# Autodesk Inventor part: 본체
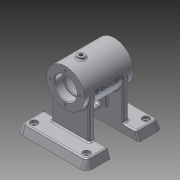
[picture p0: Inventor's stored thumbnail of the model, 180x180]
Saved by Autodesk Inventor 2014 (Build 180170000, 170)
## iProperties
Created: 2016-07
Part Number: 본체
Material: 알루미늄 6061
Document SubType Name: Modeling
Designer: USER
Density: 2.71 g/cm^3
Appearance: 알루미늄 - 평지
Mass: 500.05 g
Surface Area: 540.599 cm^2
Volume: 184.52 cm^3
Author: USER
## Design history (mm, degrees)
sketch "스케치1"
  geometry: L1 (0, 0)-(100, 0); L2 (100, 0)-(100, 110); L3 (100, 110)-(0, 110); L4 (0, 110)-(0, 0)
  constraints: 8 end point, 1 horizontal, 1 parallel, 1 perpendicular
  dimensions: "d0" = 100 distance of L1.start L1.end; "d1" = 110 distance of L1.end L2.end; "d2" = 100 distance of L2.end L3.end
extrude "돌출1" new body sketch "스케치1" distance "d3" = 12; taper "d4" = -20 deg
sketch "스케치2"
  geometry: L1 (4.368, 4.368)-(4.368, 105.632) reference; L2 (95.632, 105.632)-(95.632, 4.368) reference; L3 (4.368, 105.632)-(95.632, 105.632) reference; L4 (-24.368, 35)-(125.632, 35); L5 (125.632, 35)-(125.632, 75); L6 (125.632, 75)-(-24.368, 75); L7 (-24.368, 75)-(-24.368, 35); 3 further points
  constraints: 8 end point, 3 perpendicular, 2 midpoint, 1 horizontal alignment, 1 parallel
  dimensions: "d5" = 40 distance of L4.end L5.end; "d6" = 150 distance of L5.end L6.end; "d7" = 30 distance between parallel lines of L2 L5
extrude "돌출2" cut sketch "스케치2" distance "d8" = 12; taper "d9" = 0 deg
sketch "스케치3"
  geometry: L1 (95.632, 35)-(4.368, 35) reference; L2 (95.632, 4.368)-(4.368, 4.368) reference; L3 (4.368, 75)-(95.632, 75) reference; L4 (95.632, 105.632)-(95.632, 75) reference; L5 (4.368, 105.632)-(95.632, 105.632) reference; L6 (4.368, 75)-(4.368, 105.632) reference; L7 (23, 35)-(23, 27); L8 (23, 27)-(77, 27); L9 (77, 27)-(77, 35); L10 (23, 35)-(77, 35); L11 (23, 75)-(23, 83); L12 (23, 83)-(77, 83); L13 (77, 83)-(77, 75); L14 (23, 75)-(77, 75); 5 further points
  constraints: 16 end point, 4 midpoint, 4 perpendicular, 4 point on line, 2 collinear, 2 parallel, 2 vertical alignment
  dimensions: "d10" = 8 distance of L7.start L7.end; "d11" = 54 distance of L7.end L8.end; "d12" = 8 distance of L11.start L11.end; "d13" = 54 distance of L11.end L12.end
extrude "돌출3" join sketch "스케치3" distance "d14" = 58; taper "d15" = 0 deg
node "작업 평면1"
sketch "스케치4"
  geometry: L1 (-23, -12)-(-18.632, 0) reference; L2 (77, -12)-(-23, -12) reference; L3 (72.632, 0)-(77, -12) reference; L4 (54, 0)-(72.632, 0) reference; L5 (54, 0)-(54, 58) reference; L6 (0, 58)-(54, 58) reference; L7 (0, 0)-(0, 58) reference; L8 (-18.632, 0)-(0, 0) reference; C1 r 27 at (27, 58); 2 further points
  constraints: 2 coincident, 1 centre point, 1 midpoint
  dimensions: "d16" = 54 diameter of C1
extrude "돌출4" join sketch "스케치4" stored distance "d17" = 70; taper "d18" = 0 deg
node "작업 평면2"
sketch "스케치5"
  geometry: L1 (-85, -7)-(-31, -7) reference; L2 (-31, 63)-(-85, 63) reference; L3 (-58, 0)-(-58, 8) reference; L4 (-58, 8)-(-58, 8) reference; L5 (-58, 8)-(-58, 0) reference; L6 (-58, 0)-(-58, 0) reference; L7 (-58, 56)-(-58, 48) reference; L8 (-58, 48)-(-58, 48) reference; L9 (-58, 48)-(-58, 56) reference; L10 (-58, 56)-(-58, 56) reference; L11 (0, 0)-(0, 8) reference; L12 (0, 0)-(-58, 0) reference; L13 (-58, 8)-(-58, 0) reference; L14 (0, 8)-(-58, 8) reference; L15 (0, 48)-(0, 56) reference; L16 (0, 48)-(-58, 48) reference; L17 (-58, 56)-(-58, 48) reference; L18 (0, 56)-(-58, 56) reference; L19 (-85, 63)-(-85, -7) reference; L20 (-31, 63)-(-31, -7) reference; L21 (-10, 8)-(-10, 48); L22 (-58, 8)-(-10, 8); L23 (-58, 48)-(-10, 48); L24 (-58, 8)-(-58, 48); 1 further point
  constraints: 8 end point, 2 collinear, 2 perpendicular, 2 point on line
  dimensions: "d20" = 48 distance of L13.start L21.start
extrude "돌출5" join sketch "스케치5" stored distance "d21" = 8; taper "d22" = 0 deg
sketch "스케치6"
  geometry: L1 (31.298, 48)-(31.298, 8) reference; L2 (10, 48)-(10, 8) reference; L3 (20, 36)-(20, 20); L4 (16.5, 36)-(16.5, 20); L5 (23.5, 20)-(23.5, 36); L6 (-12, 8)-(-12, -27) reference; A1 r 3.5 centre (20, 36) between (23.5, 36) and (16.5, 36); A2 r 3.5 centre (20, 20) between (16.5, 20) and (23.5, 20); 2 further points
  constraints: 8 end point, 4 point on circle, 4 tangent, 2 centre point, 2 midpoint, 2 parallel, 1 horizontal alignment
  dimensions: "d23" = 3.5 radius of A2; "d24" = 23 dimension on A2 A1; "d25" = 32 distance from line of point (20, 28) L6
extrude "돌출6" cut sketch "스케치6" distance "d26" = 8; taper "d27" = 0 deg
sketch "스케치7"
  geometry: C1 r 27 at (0, 0) reference; C2 r 16 at (0, 0); 1 further point
  constraints: 1 centre point, 1 coincident
  dimensions: "d28" = 32 diameter of C2
extrude "돌출7" cut sketch "스케치7" distance "d29" = 12; taper "d30" = 0 deg
sketch "스케치8"
  geometry: C1 r 27 at (0, 0) reference; C2 r 16 at (0, 0); 1 further point
  constraints: 1 centre point, 1 coincident
  dimensions: "d31" = 32 diameter of C2
extrude "돌출8" cut sketch "스케치8" distance "d32" = 12; taper "d33" = 0 deg
node "작업 평면3"
sketch "스케치9"
  geometry: C1 r 16 at (0, 0) reference; C2 r 22 at (0, 0); 1 further point
  constraints: 1 centre point, 1 coincident
  dimensions: "d34" = 44 diameter of C2
extrude "돌출9" cut sketch "스케치9" stored distance "d35" = 42; taper "d36" = 0 deg
sketch "스케치10"
  geometry: C1 r 16 at (0, 0) reference; C2 r 14 at (0, 0); 1 further point
  constraints: 1 centre point, 1 coincident
  dimensions: "d37" = 28 diameter of C2
extrude "돌출10" cut sketch "스케치10" stored distance "d38" = 42; taper "d39" = 0 deg
node "작업 평면5"
  node "작업 평면4"
sketch "스케치11"
  geometry: L1 (4, -20)-(4, 20) reference; L2 (27, 20)-(4, 20) reference; L3 (27, 20)-(27, 28) reference; L4 (-27, 28)-(27, 28) reference; L5 (-27, 28)-(-27, 20) reference; L6 (-4, 20)-(-27, 20) reference; L7 (-4, 20)-(-4, -20) reference; L8 (-27, -20)-(-4, -20) reference; L9 (-27, -20)-(-27, -28) reference; L10 (27, -28)-(-27, -28) reference; L11 (27, -28)-(27, -20) reference; L12 (4, -20)-(27, -20) reference; L13 (-27, -35)-(27, -35) reference; L14 (27, 35)-(-27, 35) reference; C1 r 5 at (0, -13); 2 further points
  constraints: 1 centre point, 1 midpoint, 1 vertical alignment
  dimensions: "d41" = 10 diameter of C1; "d42" = 22 distance of point (0, -35) C1.centre
extrude "돌출11" join sketch "스케치11" stored distance "d43" = 42; taper "d44" = 0 deg
sketch "스케치12"
  geometry: C1 r 5 at (0, 0) reference; 2 further points
  constraints: 1 coincident
hole "구멍1" sketch "스케치12" at (0, 0) diameter "d45" = 5.188; stored, may be unused: countersink angle "d49" = 90 deg, drill point angle "d51" = 118 deg; dims "d46" = 10, "d47" = 4, "d48" = 2, "d50" = 10
sketch "스케치13"
  geometry: L1 (100, 75)-(0, 75) reference; L2 (0, 110)-(0, 75) reference; L3 (100, 110)-(0, 110) reference; L4 (100, 75)-(100, 110) reference; L5 (0, 35)-(0, 0) reference; L6 (0, 0)-(100, 0) reference; 4 further points
  constraints: 2 horizontal alignment, 2 vertical alignment
  dimensions: "d52" = 75 distance of point (87.5, 12.5) point (12.5, 12.5); "d53" = 85 distance of point (87.5, 12.5) point (87.5, 97.5); "d56" = 12.5 distance from line of point (12.5, 12.5) L5; "d57" = 12.5 distance from line of L6 point (12.5, 12.5)
hole "구멍2" sketch "스케치13" at (12.5, 97.5), (87.5, 97.5), (87.5, 12.5), (12.5, 12.5) diameter "d58" = 6; stored, may be unused: countersink angle "d62" = 90 deg, drill point angle "d64" = 118 deg; dims "d59" = 10, "d60" = 10, "d61" = 4, "d63" = 10
node "작업 평면6"
sketch "스케치14"
  geometry: L1 (0, 0)-(0, -27); L2 (0, 0)-(14.308, -22.897); C1 r 16 at (0, 0) reference; A1 r 27 centre (0, 0) between (4, -26.702) and (27, 0) reference; A2 r 27 centre (0, 0) between (-27, 0) and (27, 0) reference; A3 r 27 centre (0, 0) between (0, -27) and (14.308, -22.897) reference; 2 further points
  constraints: 4 end point, 4 point on circle, 1 coincident
  dimensions: "d66" = 32 deg angle of L1 L2
  node "투영된 루프9"
node "작업 평면7"
sketch "스케치17" dims "d77" = 42
  geometry: C1 r 16 at (0, 0) reference; C2 r 27 at (0, 0) reference; 3 further points
  constraints: 2 vertical alignment, 1 coincident, 2 other
hole "구멍4" sketch "스케치17" at (0, 21) diameter "d78" = 3.459; stored, may be unused: countersink angle "d82" = 90 deg, drill point angle "d84" = 118 deg; dims "d79" = 8, "d80" = 10, "d81" = 4, "d83" = 10
node "작업 평면8"
node "작업 평면9"
sketch "스케치18"
  geometry: L1 (35, 27)-(-35, 27) reference; L2 (35, -27)-(35, 27) reference; L3 (-35, 27)-(-35, -27) reference; L4 (35, -27)-(-35, -27) reference; 2 further points
  constraints: 1 other
  dimensions: "d88" = 27 distance from line of L1 point (0, 0); "d89" = 35 distance from line of L3 point (0, 0)
feature "엠보싱1" sketch "스케치18" dims "d90" = 0.5, "d91" = 0
node "작업 평면10"
sketch "스케치19"
  geometry: L1 (0, 0)-(0, -27); L2 (0, 0)-(-14.308, -22.897); C1 r 1.73 at (21, 0) reference; C2 r 1.73 at (0, -21) reference; C3 r 1.73 at (-21, 0) reference; C4 r 1.73 at (0, 21) reference; C5 r 16 at (0, 0) reference; A1 r 27 centre (0, 0) between (-14.308, -22.897) and (0, -27) reference; 2 further points
  constraints: 4 end point, 2 point on circle, 1 coincident, 1 vertical
  dimensions: "d92" = 32 deg angle of L1 L2
  node "투영된 루프12"
node "작업 평면11"
sketch "스케치20"
  geometry: L1 (-14.566, -21.692)-(-17.463, -21.692) reference; L2 (-17.463, -21.692)-(-17.463, -21.912) reference; L3 (-17.463, -21.912)-(-15.014, -21.912) reference; L4 (-15.014, -21.912)-(-15.014, -22.577) reference; L5 (-15.014, -22.577)-(-17.198, -22.577) reference; L6 (-17.198, -22.577)-(-17.198, -22.78) reference; L7 (-17.198, -22.78)-(-15.014, -22.78) reference; L8 (-15.014, -22.78)-(-15.014, -23.456) reference; L9 (-14.566, -23.651)-(-14.566, -21.692) reference; L10 (-9.803, -22.152)-(-10.834, -22.152) reference; L11 (-10.834, -22.152)-(-10.834, -21.265) reference; L12 (-10.834, -21.265)-(-11.208, -21.265) reference; L13 (-11.289, -21.41)-(-11.289, -23.615) reference; L14 (-11.289, -23.615)-(-10.834, -23.615) reference; L15 (-10.834, -23.615)-(-10.834, -22.348) reference; L16 (-10.834, -22.348)-(-9.803, -22.348) reference; L17 (-9.803, -22.348)-(-9.803, -22.152) reference; L18 (-8.67, -21.381)-(-9.071, -21.381) reference; L19 (0.488, -24.174)-(0.488, -21.793) reference; L20 (0.488, -21.793)-(2.042, -21.793) reference; L21 (2.042, -21.793)-(2.042, -21.546) reference; L22 (2.042, -21.546)-(-1.526, -21.546) reference; L23 (-1.526, -21.546)-(-1.526, -21.793) reference; L24 (-1.526, -21.793)-(0.034, -21.793) reference; L25 (0.034, -21.793)-(0.034, -24.174) reference; L26 (0.034, -24.174)-(0.488, -24.174) reference; L27 (4.878, -21.546)-(4.335, -21.546) reference; L28 (2.436, -24.174)-(2.917, -24.174) reference; L29 (3.474, -23.456)-(5.726, -23.456) reference; L30 (6.296, -24.174)-(6.777, -24.174) reference; L31 (18.853, -21.307)-(17.374, -21.307) reference; L32 (17.374, -21.307)-(17.374, -21.521) reference; L33 (17.374, -21.521)-(18.853, -21.521) reference; L34 (18.853, -21.521)-(18.853, -21.307) reference; L35 (15.061, -21.332)-(15.061, -22.547) reference; L36 (15.061, -22.547)-(13.942, -22.547) reference; L37 (13.942, -22.547)-(13.942, -22.761) reference; L38 (13.942, -22.761)-(15.061, -22.761) reference; L39 (15.061, -22.761)-(15.061, -23.651) reference; L40 (15.061, -23.651)-(15.536, -23.651) reference; L41 (15.536, -23.651)-(15.536, -21.168) reference; L42 (15.536, -21.168)-(15.231, -21.168) reference; L43 (18.731, -23.612)-(18.731, -24.095) reference; L44 (18.731, -24.095)-(14.844, -24.095) reference; L45 (14.844, -24.095)-(14.844, -24.264) reference; L46 (14.844, -24.264)-(19.193, -24.264) reference; L47 (19.193, -24.264)-(19.193, -23.506) reference; L48 (19.193, -23.506)-(18.84, -23.506) reference; L49 (20.047, -21.793)-(16.282, -21.793) reference; L50 (16.282, -21.793)-(16.282, -21.999) reference; L51 (16.282, -21.999)-(20.047, -21.999) reference; L52 (20.047, -21.999)-(20.047, -21.793) reference; L53 (13.311, -22.495)-(8.942, -22.495) reference; L54 (8.657, -21.53)-(12.463, -21.53) reference; L55 (12.463, -21.53)-(12.463, -21.298) reference; L56 (12.463, -21.298)-(8.175, -21.298) reference; L57 (8.446, -22.495)-(7.307, -22.495) reference; L58 (7.307, -22.495)-(7.307, -22.699) reference; L59 (7.307, -22.699)-(10.095, -22.699) reference; L60 (10.095, -22.699)-(10.095, -23.337) reference; L61 (10.095, -23.337)-(8.284, -23.337) reference; L62 (8.284, -23.337)-(8.284, -24.332) reference; L63 (8.284, -24.332)-(8.745, -24.332) reference; L64 (8.745, -24.332)-(8.745, -23.522) reference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; C1 r 6 at (0, 0); 63 further points
  constraints: 2 midpoint, 1 centre point, 1 horizontal alignment, 1 vertical alignment, 76 other
  dimensions: "d93" = 12 diameter of C1
extrude "돌출13" join sketch "스케치20" stored distance "d94" = 6; taper "d95" = 0 deg
sketch "스케치21"
  geometry: C1 r 6 at (0, 0) reference; 2 further points
  constraints: 1 coincident
hole "구멍5" sketch "스케치21" at (0, 0) diameter "d96" = 5.188; stored, may be unused: countersink angle "d100" = 90 deg, drill point angle "d102" = 118 deg; dims "d97" = 10, "d98" = 10, "d99" = 4, "d101" = 10
fillet "모깎기1" dims "d103" = 10, "d104" = 5, "d105" = 10, "d106" = 5, "d107" = 10, "d108" = 5, "d109" = 10, "d110" = 5
fillet "모깎기2" dims "d111" = 2
chamfer "모따기1" distance "d112" = 1; stored, may be unused: second distance "d113" = 2, angle "d114" = 45 deg
fillet "모깎기3" dims "d115" = 3
fillet "모깎기4" dims "d116" = 0.3
node "솔리드1"
pattern_circular "원형 패턴1" dims angle "d86" = 360 deg
mirror "대칭1"
node "투영된 루프1"
node "투영된 루프2"
node "투영된 루프3"
node "투영된 루프4"
node "투영된 루프5"
node "투영된 루프6"
node "투영된 루프7"
node "투영된 루프8"
node "투영된 루프13"
other parameters: "d40" = 3
